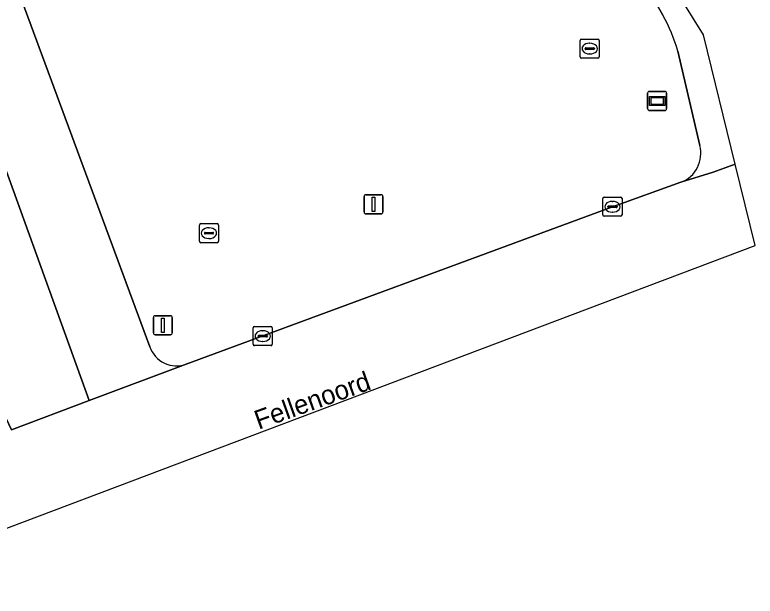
# Model space of a CAD drawing. Extents: x 160304 to 160955, y 383684 to 384161.
# Drawn here: x 160916.68 to 160955.36, y 383812.71 to 383843.09 of the extents above; entities that cross this region are included whole.
import ezdxf

# ---------------------------------------------------------------- set-up
doc = ezdxf.new("R2010")
doc.units = 0
for name, color, linetype in [('IMGEO_Brandkraan', 7, 'Continuous'), ('IMGEO_Groenvoorziening', 7, 'Continuous'), ('IMGEO_Kolk', 7, 'Continuous'), ('IMGEO_Lichtmast', 7, 'Continuous'), ('IMGEO_Openbare_ruimte_label', 7, 'Continuous'), ('IMGEO_Rijbaan_lokaal_gesloten', 7, 'Continuous'), ('IMGEO_Rioolput', 7, 'Continuous'), ('IMGEO_Verkeersregelinstallatiepaal', 7, 'Continuous'), ('IMGEO_Verklikker', 7, 'Continuous')]:
    doc.layers.add(name, color=color, linetype=linetype)

msp = doc.modelspace()

# ---------------------------------------------------------------- linework, layer by layer
at = {"layer": 'IMGEO_Brandkraan'}
for p, q in [((160946.209, 383840.899), (160946.209, 383841.751)), ((160946.284, 383841.825), (160947.136, 383841.825)), ((160946.697, 383841.605), (160946.722, 383841.605)), ((160947.21, 383841.751), (160947.21, 383840.899)), ((160946.468, 383841.319), (160946.468, 383841.331)), ((160946.906, 383841.282), (160946.508, 383841.282)), ((160946.511, 383841.368), (160946.909, 383841.368)), ((160946.952, 383841.331), (160946.952, 383841.319)), ((160947.136, 383840.825), (160946.284, 383840.825)), ((160946.72, 383841.045), (160946.695, 383841.045))]:
    msp.add_line(p, q, dxfattribs=at)
for points in [[(160946.209, 383840.899), (160946.209, 383841.751)], [(160946.284, 383841.825), (160947.136, 383841.825)], [(160947.21, 383841.751), (160947.21, 383840.899)], [(160947.136, 383840.825), (160946.284, 383840.825)]]:
    msp.add_lwpolyline(points, dxfattribs=at)
for centre, radius, start, end in [((160946.286, 383841.749), 0.0765, 91.552, 178.448), ((160946.286, 383841.749), 0.0765, 91.552, 178.448), ((160947.134, 383841.749), 0.0765, 1.552, 88.448), ((160947.134, 383841.749), 0.0765, 1.552, 88.448), ((160946.508, 383841.328), 0.0403, 85.8775, 175.7526), ((160946.505, 383841.318), 0.0366, 178.938, 274.7102), ((160946.909, 383841.325), 0.043, 264.8664, 352.4533), ((160946.913, 383841.33), 0.0386, 1.7309, 96.639), ((160946.286, 383840.901), 0.0765, 181.552, 268.448), ((160946.286, 383840.901), 0.0765, 181.552, 268.448), ((160947.134, 383840.901), 0.0765, 271.552, 358.448), ((160947.134, 383840.901), 0.0765, 271.552, 358.448)]:
    msp.add_arc(centre, radius, start, end, dxfattribs=at)
for centre, major_axis, ratio, start_param, end_param in [((160946.696, 383841.325), (-0.387, 0.002), 0.722429, 4.712389, 7.853982), ((160946.721, 383841.325), (-0.39, 0.002), 0.717154, 1.570796, 4.712389)]:
    msp.add_ellipse(centre, major_axis=major_axis, ratio=ratio, start_param=start_param, end_param=end_param, dxfattribs=at)
at = {"layer": 'IMGEO_Groenvoorziening'}
for points in [[(160950.531, 383843.067), (160949.052, 383845.722), (160948.035, 383847.457), (160945.108, 383852.141), (160917.077, 383897.29)], [(160902.173, 383884.035), (160923.728, 383825.74)], [(160952.457, 383836.271), (160951.321, 383841.189)], [(160925.63, 383824.832), (160947.895, 383833.061), (160951.471, 383834.342)]]:
    msp.add_lwpolyline(points, dxfattribs=at)
for centre, radius, start, end in [((160942.132, 383838.429), 9.595, 16.72, 28.9092), ((160950.915, 383835.842), 1.6, 290.3178, 15.5349), ((160925.131, 383826.233), 1.487, 199.352, 289.6091)]:
    msp.add_arc(centre, radius, start, end, dxfattribs=at)
at = {"layer": 'IMGEO_Kolk'}
for p, q in [((160947.398, 383832.636), (160947.398, 383833.488)), ((160947.473, 383833.562), (160948.325, 383833.562)), ((160947.886, 383833.342), (160947.911, 383833.342)), ((160948.399, 383833.488), (160948.399, 383832.636)), ((160947.657, 383833.056), (160947.657, 383833.068)), ((160948.095, 383833.019), (160947.697, 383833.019)), ((160947.7, 383833.105), (160948.098, 383833.105)), ((160948.141, 383833.068), (160948.141, 383833.056)), ((160948.325, 383832.562), (160947.473, 383832.562)), ((160947.909, 383832.782), (160947.884, 383832.782)), ((160929.201, 383826.803), (160930.053, 383826.803)), ((160929.126, 383825.877), (160929.126, 383826.729)), ((160929.614, 383826.583), (160929.639, 383826.583)), ((160930.127, 383826.729), (160930.127, 383825.877)), ((160929.385, 383826.297), (160929.385, 383826.309)), ((160929.823, 383826.26), (160929.425, 383826.26)), ((160929.428, 383826.346), (160929.826, 383826.346)), ((160929.637, 383826.023), (160929.612, 383826.023)), ((160929.869, 383826.309), (160929.869, 383826.297)), ((160930.053, 383825.803), (160929.201, 383825.803))]:
    msp.add_line(p, q, dxfattribs=at)
for points in [[(160947.398, 383832.636), (160947.398, 383833.488)], [(160947.473, 383833.562), (160948.325, 383833.562)], [(160948.399, 383833.488), (160948.399, 383832.636)], [(160948.325, 383832.562), (160947.473, 383832.562)], [(160929.201, 383826.803), (160930.053, 383826.803)], [(160929.126, 383825.877), (160929.126, 383826.729)], [(160930.127, 383826.729), (160930.127, 383825.877)], [(160930.053, 383825.803), (160929.201, 383825.803)]]:
    msp.add_lwpolyline(points, dxfattribs=at)
for centre, radius, start, end in [((160947.475, 383833.486), 0.0765, 91.552, 178.448), ((160947.475, 383833.486), 0.0765, 91.552, 178.448), ((160948.323, 383833.486), 0.0765, 1.552, 88.448), ((160948.323, 383833.486), 0.0765, 1.552, 88.448), ((160947.697, 383833.065), 0.0403, 85.8775, 175.7526), ((160947.694, 383833.055), 0.0366, 178.938, 274.7102), ((160948.098, 383833.062), 0.043, 264.8664, 352.4533), ((160948.102, 383833.067), 0.0386, 1.7309, 96.639), ((160947.475, 383832.638), 0.0765, 181.552, 268.448), ((160947.475, 383832.638), 0.0765, 181.552, 268.448), ((160948.323, 383832.638), 0.0765, 271.552, 358.448), ((160948.323, 383832.638), 0.0765, 271.552, 358.448), ((160929.203, 383826.727), 0.0765, 91.552, 178.448), ((160929.203, 383826.727), 0.0765, 91.552, 178.448), ((160930.051, 383826.727), 0.0765, 1.552, 88.448), ((160930.051, 383826.727), 0.0765, 1.552, 88.448), ((160929.425, 383826.306), 0.0403, 85.8775, 175.7526), ((160929.422, 383826.296), 0.0366, 178.938, 274.7102), ((160929.826, 383826.303), 0.043, 264.8664, 352.4533), ((160929.83, 383826.308), 0.0386, 1.7309, 96.639), ((160929.203, 383825.879), 0.0765, 181.552, 268.448), ((160929.203, 383825.879), 0.0765, 181.552, 268.448), ((160930.051, 383825.879), 0.0765, 271.552, 358.448), ((160930.051, 383825.879), 0.0765, 271.552, 358.448)]:
    msp.add_arc(centre, radius, start, end, dxfattribs=at)
for centre, major_axis, ratio, start_param, end_param in [((160947.885, 383833.062), (-0.387, 0.002), 0.722429, 4.712389, 7.853982), ((160947.91, 383833.062), (-0.39, 0.002), 0.717154, 1.570796, 4.712389), ((160929.613, 383826.303), (-0.387, 0.002), 0.722429, 4.712389, 7.853982), ((160929.638, 383826.303), (-0.39, 0.002), 0.717154, 1.570796, 4.712389)]:
    msp.add_ellipse(centre, major_axis=major_axis, ratio=ratio, start_param=start_param, end_param=end_param, dxfattribs=at)
at = {"layer": 'IMGEO_Lichtmast'}
for p, q in [((160934.919, 383832.79), (160934.919, 383833.59)), ((160934.919, 383833.59), (160934.919, 383832.79)), ((160935.019, 383833.69), (160935.809, 383833.69)), ((160935.809, 383833.69), (160935.019, 383833.69)), ((160935.909, 383833.59), (160935.909, 383832.79)), ((160935.909, 383832.79), (160935.909, 383833.59)), ((160935.809, 383832.69), (160935.019, 383832.69)), ((160935.019, 383832.69), (160935.809, 383832.69))]:
    msp.add_line(p, q, dxfattribs=at)
msp.add_lwpolyline([(160935.339, 383833.565), (160935.489, 383833.565), (160935.489, 383832.815), (160935.339, 383832.815), (160935.339, 383833.565)], dxfattribs=at)
for centre, start, end in [((160935.019, 383833.59), 90, 180), ((160935.019, 383833.59), 90, 180), ((160935.809, 383833.59), 0, 90), ((160935.809, 383833.59), 360, 90), ((160935.019, 383832.79), 180, 270), ((160935.019, 383832.79), 180, 270), ((160935.809, 383832.79), 270, 0), ((160935.809, 383832.79), 270, 0)]:
    msp.add_arc(centre, 0.1, start, end, dxfattribs=at)
at = {"layer": 'IMGEO_Rijbaan_lokaal_gesloten'}
for points in [[(160954.311, 383835.295), (160952.654, 383842.04), (160901.725, 383923.859), (160900.833, 383923.408), (160917.077, 383897.29), (160945.108, 383852.141), (160948.035, 383847.457), (160949.052, 383845.722), (160950.531, 383843.067)], [(160887.955, 383916.832), (160887.859, 383917.022), (160884.917, 383915.524), (160887.049, 383911.378), (160893.201, 383897.836), (160897.631, 383886.88), (160907.713, 383858.522), (160920.564, 383822.935), (160925.63, 383824.832)], [(160916.208, 383822.031), (160916.497, 383821.396), (160920.564, 383822.935), (160907.713, 383858.522), (160897.631, 383886.88), (160893.201, 383897.836), (160887.049, 383911.378), (160884.917, 383915.524)], [(160923.728, 383825.74), (160902.173, 383884.035)], [(160951.321, 383841.189), (160952.457, 383836.271)], [(160906.846, 383812.711), (160955.355, 383831.043), (160954.311, 383835.295), (160953.158, 383834.864), (160951.471, 383834.342), (160947.895, 383833.061), (160925.63, 383824.832), (160920.564, 383822.935), (160916.497, 383821.396), (160916.208, 383822.031)], [(160951.471, 383834.342), (160953.158, 383834.864), (160954.311, 383835.295)]]:
    msp.add_lwpolyline(points, dxfattribs=at)
for centre, radius, start, end in [((160942.132, 383838.429), 9.595, 16.72, 28.9092), ((160950.915, 383835.842), 1.6, 290.3178, 15.5349), ((160925.131, 383826.233), 1.487, 199.352, 289.6091)]:
    msp.add_arc(centre, radius, start, end, dxfattribs=at)
at = {"layer": 'IMGEO_Rioolput'}
for p, q in [((160926.394, 383832.182), (160927.246, 383832.182)), ((160926.319, 383831.256), (160926.319, 383832.108)), ((160926.807, 383831.962), (160926.832, 383831.962)), ((160927.32, 383832.108), (160927.32, 383831.256)), ((160926.578, 383831.676), (160926.578, 383831.688)), ((160927.016, 383831.639), (160926.618, 383831.639)), ((160926.621, 383831.725), (160927.019, 383831.725)), ((160926.83, 383831.402), (160926.805, 383831.402)), ((160927.062, 383831.688), (160927.062, 383831.676)), ((160927.246, 383831.182), (160926.394, 383831.182))]:
    msp.add_line(p, q, dxfattribs=at)
for points in [[(160926.394, 383832.182), (160927.246, 383832.182)], [(160926.319, 383831.256), (160926.319, 383832.108)], [(160927.32, 383832.108), (160927.32, 383831.256)], [(160927.246, 383831.182), (160926.394, 383831.182)]]:
    msp.add_lwpolyline(points, dxfattribs=at)
for centre, radius, start, end in [((160926.396, 383832.106), 0.0765, 91.552, 178.448), ((160926.396, 383832.106), 0.0765, 91.552, 178.448), ((160927.244, 383832.106), 0.0765, 1.552, 88.448), ((160927.244, 383832.106), 0.0765, 1.552, 88.448), ((160926.618, 383831.685), 0.0403, 85.8775, 175.7526), ((160926.615, 383831.675), 0.0366, 178.938, 274.7102), ((160927.019, 383831.682), 0.043, 264.8664, 352.4533), ((160927.023, 383831.687), 0.0386, 1.7309, 96.639), ((160926.396, 383831.258), 0.0765, 181.552, 268.448), ((160926.396, 383831.258), 0.0765, 181.552, 268.448), ((160927.244, 383831.258), 0.0765, 271.552, 358.448), ((160927.244, 383831.258), 0.0765, 271.552, 358.448)]:
    msp.add_arc(centre, radius, start, end, dxfattribs=at)
for centre, major_axis, ratio, start_param, end_param in [((160926.806, 383831.682), (-0.387, 0.002), 0.722429, 4.712389, 7.853982), ((160926.831, 383831.682), (-0.39, 0.002), 0.717154, 1.570796, 4.712389)]:
    msp.add_ellipse(centre, major_axis=major_axis, ratio=ratio, start_param=start_param, end_param=end_param, dxfattribs=at)
at = {"layer": 'IMGEO_Verkeersregelinstallatiepaal'}
for p, q in [((160923.915, 383826.47), (160923.915, 383827.27)), ((160923.915, 383827.27), (160923.915, 383826.47)), ((160924.015, 383827.37), (160924.805, 383827.37)), ((160924.805, 383827.37), (160924.015, 383827.37)), ((160924.905, 383827.27), (160924.905, 383826.47)), ((160924.905, 383826.47), (160924.905, 383827.27)), ((160924.805, 383826.37), (160924.015, 383826.37)), ((160924.015, 383826.37), (160924.805, 383826.37))]:
    msp.add_line(p, q, dxfattribs=at)
msp.add_lwpolyline([(160924.335, 383827.245), (160924.485, 383827.245), (160924.485, 383826.495), (160924.335, 383826.495), (160924.335, 383827.245)], dxfattribs=at)
for centre, start, end in [((160924.015, 383827.27), 90, 180), ((160924.015, 383827.27), 90, 180), ((160924.805, 383827.27), 0, 90), ((160924.805, 383827.27), 360, 90), ((160924.015, 383826.47), 180, 270), ((160924.015, 383826.47), 180, 270), ((160924.805, 383826.47), 270, 0), ((160924.805, 383826.47), 270, 0)]:
    msp.add_arc(centre, 0.1, start, end, dxfattribs=at)
at = {"layer": 'IMGEO_Verklikker'}
for p, q in [((160949.737, 383838.19), (160949.737, 383838.99)), ((160949.737, 383838.99), (160949.737, 383838.19)), ((160949.837, 383839.09), (160950.627, 383839.09)), ((160950.627, 383839.09), (160949.837, 383839.09)), ((160950.727, 383838.99), (160950.727, 383838.19)), ((160950.727, 383838.19), (160950.727, 383838.99)), ((160950.627, 383838.09), (160949.837, 383838.09)), ((160949.837, 383838.09), (160950.627, 383838.09))]:
    msp.add_line(p, q, dxfattribs=at)
for points in [[(160949.838, 383838.822), (160950.626, 383838.822), (160950.626, 383838.358), (160949.838, 383838.358), (160949.838, 383838.822)], [(160949.903, 383838.757), (160949.903, 383838.423), (160950.561, 383838.423), (160950.561, 383838.757), (160949.903, 383838.757)]]:
    msp.add_lwpolyline(points, dxfattribs=at)
for centre, start, end in [((160949.837, 383838.99), 90, 180), ((160949.837, 383838.99), 90, 180), ((160950.627, 383838.99), 0, 90), ((160950.627, 383838.99), 360, 90), ((160949.837, 383838.19), 180, 270), ((160949.837, 383838.19), 180, 270), ((160950.627, 383838.19), 270, 0), ((160950.627, 383838.19), 270, 0)]:
    msp.add_arc(centre, 0.1, start, end, dxfattribs=at)

# ---------------------------------------------------------------- texts
at = {"layer": 'IMGEO_Openbare_ruimte_label'}
msp.add_text('Fellenoord', height=1, rotation=19.7579, dxfattribs=at).set_placement((160929.413, 383821.405))

doc.saveas('drawing.dxf')
